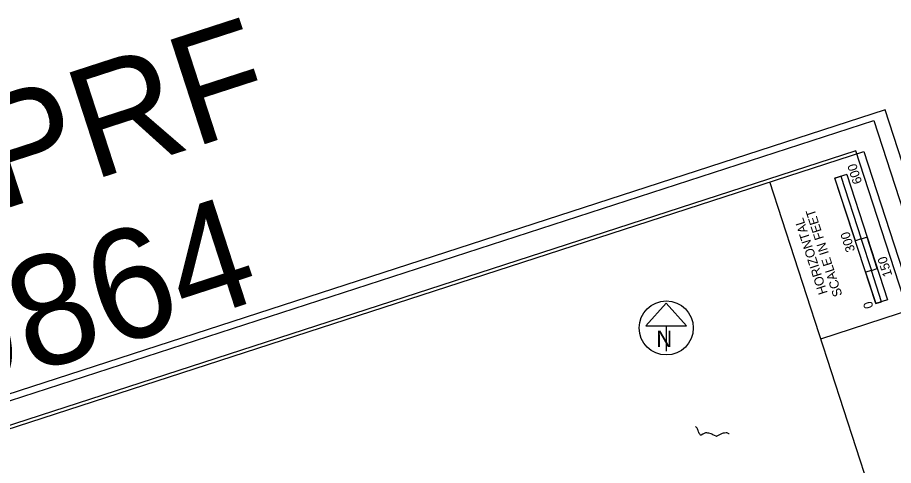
# Model space of a CAD drawing. Extents: x -468548933 to 3387700, y -306089263 to 1207014.
# Drawn here: x 1838071 to 1842053, y 539541 to 541579 of the extents above; entities that cross this region are included whole.
import ezdxf

# ---------------------------------------------------------------- set-up
doc = ezdxf.new("R2010")
doc.units = 0
for name, color, linetype in [('DT_X_Contour_Minor', 7, 'Continuous'), ('DT_X_Terrain_Ground_Line', 7, 'Continuous'), ('Level 63', 7, 'Continuous'), ('SH_Border', 7, 'Continuous'), ('SH_Cut_Line', 7, 'Continuous'), ('SH_Data', 7, 'Continuous'), ('SH_Masking', 7, 'Continuous'), ('SH_Text', 7, 'Continuous')]:
    doc.layers.add(name, color=color, linetype=linetype)

msp = doc.modelspace()

# ---------------------------------------------------------------- linework, layer by layer
at = {"layer": 'DT_X_Contour_Minor'}
msp.add_lwpolyline([(1841305.6, 539684.2), (1841305, 539684.6), (1841302, 539686.8), (1841299.2, 539688.4), (1841296, 539689.1), (1841292.3, 539689.1), (1841283.9, 539688.5), (1841279.2, 539687.8), (1841273.8, 539686.2), (1841267.9, 539683.3), (1841250.4, 539673.5), (1841248.6, 539673.2), (1841246.4, 539673.8), (1841239, 539677.1), (1841232, 539680.6), (1841226.7, 539683.5), (1841224.1, 539684.6), (1841213.4, 539687.1), (1841209, 539688.6), (1841204.2, 539689.7), (1841198.7, 539689.3), (1841192.4, 539687), (1841186.3, 539683.6), (1841178, 539678.6), (1841175.9, 539678.3), (1841174.1, 539679.6), (1841172, 539682.6), (1841169.7, 539686.5), (1841167.8, 539690.6), (1841166.6, 539694.1), (1841165, 539700.4), (1841163.8, 539703.7), (1841162.1, 539707.2), (1841159.9, 539710.6), (1841157, 539713.9), (1841153.7, 539716.9), (1841153.2, 539717.2)], dxfattribs=at)
at = {"layer": 'Level 63'}
for points in [[(1832262, 537961.5), (1841962.9, 541110.9), (1844000.6, 534834.2), (1834299.8, 531684.7)], [(1834368.8, 531858.5), (1843842, 534934.1), (1841881.8, 540971.9), (1832408.6, 537896.3)]]:
    msp.add_lwpolyline(points, close=True, dxfattribs=at)
at = {"layer": 'SH_Border'}
for p, q in [((1843436.2, 534838.5), (1841490.8, 540830.6)), ((1841722.4, 540117.3), (1842150.4, 540256.3))]:
    msp.add_line(p, q, dxfattribs=at)
msp.add_lwpolyline([(1832787.9, 538005.2), (1841918.8, 540969.6), (1843864.2, 534977.5), (1834733.3, 532013.1)], close=True, dxfattribs=at)
at = {"layer": 'SH_Cut_Line'}
msp.add_lwpolyline([(1834351.6, 531731.5), (1844053.2, 534881.1), (1842015.1, 541158.6), (1832313.6, 538008.9)], close=True, dxfattribs=at)
at = {"layer": 'SH_Data'}
for p, q in [((1841840.4, 540865.3), (1841786.9, 540847.9)), ((1841786.9, 540847.9), (1841813.6, 540856.6)), ((1841972.2, 540277.3), (1841786.9, 540847.9)), ((1841879.6, 540562.6), (1841786.9, 540847.9)), ((1841813.6, 540856.6), (1841813.8, 540856.7)), ((1841813.8, 540856.7), (1841906.4, 540571.3)), ((1841840.4, 540865.3), (1842025.7, 540294.6)), ((1841906.4, 540571.3), (1841879.6, 540562.6)), ((1841932.8, 540579.9), (1841906.2, 540571.2)), ((1841906.2, 540571.2), (1841952.5, 540428.6)), ((1841979.1, 540437.2), (1841932.8, 540579.9)), ((1841952.5, 540428.6), (1841979.1, 540437.2)), ((1841952.5, 540428.6), (1841925.9, 540419.9)), ((1841925.9, 540419.9), (1841972.2, 540277.3)), ((1841998.8, 540285.9), (1841952.5, 540428.6)), ((1842025.7, 540294.6), (1841972.2, 540277.3)), ((1841972.2, 540277.3), (1841998.8, 540285.9))]:
    msp.add_line(p, q, dxfattribs=at)
at = {"layer": 'SH_Masking'}
msp.add_circle((1841019.7, 540166.7), 123, dxfattribs=at)
at = {"layer": 'SH_Text'}
for p, q in [((1841019.6, 540278.9), (1840927.4, 540176.5)), ((1841111.9, 540176.5), (1841019.6, 540278.9)), ((1840927.4, 540176.5), (1841111.9, 540176.5)), ((1841019.7, 540176.5), (1841019.7, 540060.5))]:
    msp.add_line(p, q, dxfattribs=at)
msp.add_circle((1841019.7, 540166.7), 123, dxfattribs=at)

# ---------------------------------------------------------------- texts
at = {"layer": 'DT_X_Terrain_Ground_Line'}
for s, p in [('24336GB03.PRF', (1834414.4, 539539.3)), ('ROT=17.9864', (1835178.6, 538998.9))]:
    msp.add_text(s, height=500, rotation=17.9864, dxfattribs=at).set_placement(p)
at = {"layer": 'SH_Data'}
for s, p in [('600', (1841911, 540828.9)), ('SCALE IN FEET', (1841821, 540316.2)), ('HORIZONTAL', (1841753.9, 540326.3)), ('300', (1841879.2, 540518.9)), ('150', (1842048, 540406.7)), ('0', (1841962.6, 540261.9))]:
    msp.add_text(s, height=42, rotation=107.9864, dxfattribs=at).set_placement(p)
at = {"layer": 'SH_Text'}
msp.add_text('N', height=75, rotation=0.001, dxfattribs=at).set_placement((1840974.3, 540079.3))

doc.saveas('drawing.dxf')
